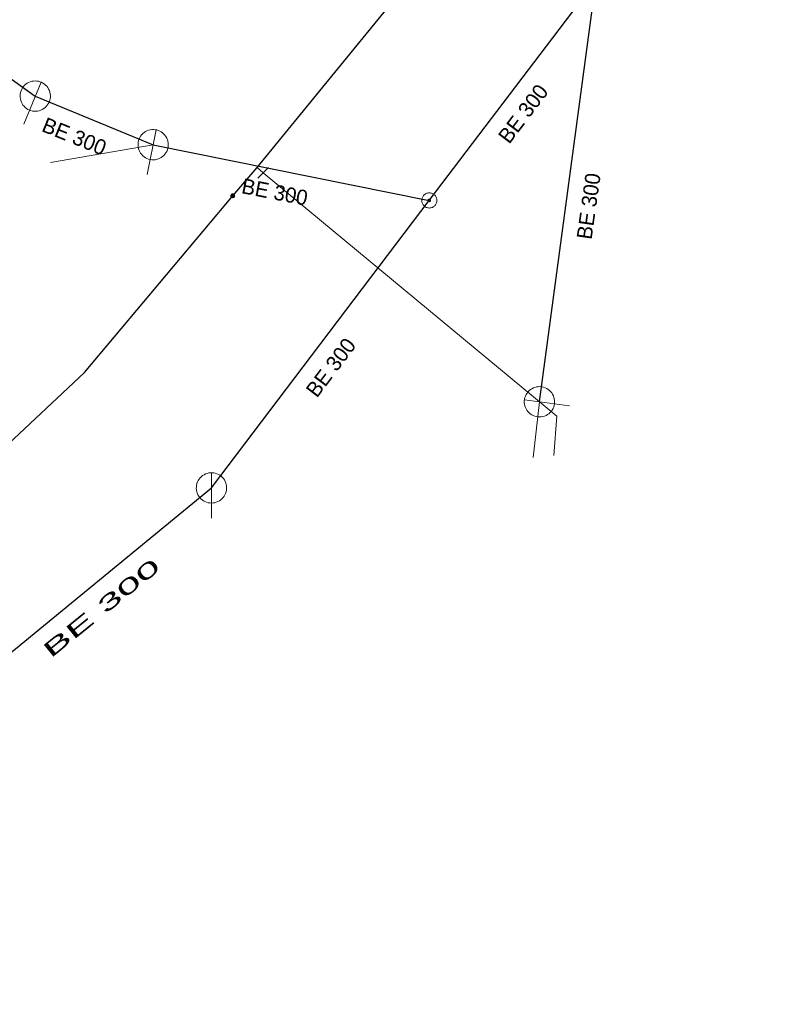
# Model space of a CAD drawing. Extents: x -791337 to -790755, y -988454 to -987923.
# Drawn here: x -791030.1 to -790980, y -988179.4 to -988115.1 of the extents above; entities that cross this region are included whole.
import ezdxf

# ---------------------------------------------------------------- set-up
doc = ezdxf.new("R2010")
doc.units = 0
doc.header["$LTSCALE"] = 0.4
for name, color, linetype, lineweight in [('1', 7, 'Continuous', 13), ('11', 7, 'Continuous', 13), ('13', 7, 'Continuous', 13), ('14', 7, 'Continuous', 25), ('17', 7, 'Continuous', 25), ('22', 7, 'Continuous', 13), ('31', 7, 'Continuous', 13), ('34', 7, 'Continuous', 13), ('9', 7, 'Continuous', 13)]:
    doc.layers.add(name, color=color, linetype=linetype, lineweight=lineweight)

msp = doc.modelspace()

# ---------------------------------------------------------------- linework, layer by layer
at = {"layer": '11'}
for p, q in [((-791028.011, -988124.594), (-791021.247, -988123.414)), ((-790996.191, -988144.061), (-790995.768, -988140.376))]:
    msp.add_line(p, q, dxfattribs=at)
at = {"layer": '13'}
msp.add_line((-791014.379, -988124.914), (-791013.989, -988125.269), dxfattribs=at)
msp.add_lwpolyline([(-791013.989, -988125.269), (-790994.62, -988141.329), (-790994.829, -988143.927)], dxfattribs=at)
at = {"layer": '14'}
for p, q in [((-790995.768, -988140.376), (-790992.035, -988112.568)), ((-791017.401, -988146.056), (-791003.034, -988127.09))]:
    msp.add_line(p, q, dxfattribs=at)
for points in [[(-791003.034, -988127.09), (-790992.035, -988112.568), (-790980, -988098.359)], [(-791052.439, -988139.196), (-791035.28, -988115.732), (-791029.024, -988120.205)], [(-791029.024, -988120.205), (-791021.247, -988123.414), (-791003.034, -988127.09)], [(-791038.46, -988179.417), (-791036.499, -988161.736), (-791017.401, -988146.056)]]:
    msp.add_lwpolyline(points, dxfattribs=at)
at = {"layer": '17'}
for points in [[(-791015.996, -988126.782), (-791014.379, -988124.914), (-791004.537, -988112.846), (-790993.489, -988096.87), (-790985.039, -988083.809)], [(-791058.988, -988167.736), (-791047.931, -988158.352), (-791041.594, -988153.292), (-791025.772, -988138.449), (-791015.996, -988126.782)]]:
    msp.add_lwpolyline(points, dxfattribs=at)
at = {"layer": '22'}
for p, q in [((-791029.786, -988122.054), (-791028.642, -988119.281)), ((-791021.642, -988125.374), (-791021.049, -988122.434)), ((-790993.785, -988140.642), (-790996.758, -988140.242)), ((-791017.401, -988148.056), (-791017.4, -988145.056))]:
    msp.add_line(p, q, dxfattribs=at)
for points in [[(-791028.099, -988120.586), (-791028.063, -988120.483), (-791028.039, -988120.377), (-791028.026, -988120.267), (-791028.024, -988120.158), (-791028.036, -988120.049), (-791028.059, -988119.942), (-791028.093, -988119.838), (-791028.139, -988119.739), (-791028.195, -988119.644), (-791028.261, -988119.558), (-791028.337, -988119.478), (-791028.421, -988119.408), (-791028.512, -988119.346), (-791028.609, -988119.296), (-791028.711, -988119.255), (-791028.816, -988119.227), (-791028.925, -988119.21), (-791029.034, -988119.204), (-791029.143, -988119.212), (-791029.25, -988119.231), (-791029.356, -988119.262), (-791029.457, -988119.304), (-791029.553, -988119.357), (-791029.643, -988119.419), (-791029.725, -988119.492), (-791029.798, -988119.573), (-791029.863, -988119.662), (-791029.917, -988119.756), (-791029.961, -988119.857), (-791029.993, -988119.962), (-791030.015, -988120.069), (-791030.023, -988120.178), (-791030.02, -988120.287), (-791030.006, -988120.396), (-791029.978, -988120.502), (-791029.94, -988120.605), (-791029.891, -988120.703), (-791029.832, -988120.794), (-791029.763, -988120.879), (-791029.684, -988120.956), (-791029.598, -988121.024), (-791029.505, -988121.082), (-791029.406, -988121.129), (-791029.303, -988121.165), (-791029.196, -988121.19), (-791029.088, -988121.203), (-791028.978, -988121.204), (-791028.869, -988121.193), (-791028.762, -988121.17), (-791028.658, -988121.136), (-791028.558, -988121.09), (-791028.465, -988121.034), (-791028.377, -988120.968), (-791028.298, -988120.893), (-791028.227, -988120.809), (-791028.165, -988120.718), (-791028.115, -988120.621)], [(-791020.266, -988123.612), (-791020.251, -988123.504), (-791020.247, -988123.394), (-791020.255, -988123.285), (-791020.275, -988123.178), (-791020.306, -988123.072), (-791020.349, -988122.972), (-791020.403, -988122.876), (-791020.467, -988122.788), (-791020.54, -988122.706), (-791020.622, -988122.633), (-791020.711, -988122.569), (-791020.807, -988122.516), (-791020.908, -988122.473), (-791021.013, -988122.442), (-791021.121, -988122.422), (-791021.229, -988122.415), (-791021.339, -988122.418), (-791021.448, -988122.434), (-791021.553, -988122.462), (-791021.655, -988122.501), (-791021.753, -988122.552), (-791021.844, -988122.612), (-791021.928, -988122.683), (-791022.004, -988122.761), (-791022.071, -988122.848), (-791022.127, -988122.941), (-791022.174, -988123.041), (-791022.209, -988123.144), (-791022.233, -988123.252), (-791022.245, -988123.36), (-791022.245, -988123.469), (-791022.233, -988123.578), (-791022.209, -988123.685), (-791022.174, -988123.789), (-791022.127, -988123.888), (-791022.07, -988123.981), (-791022.003, -988124.068), (-791021.927, -988124.147), (-791021.843, -988124.217), (-791021.751, -988124.277), (-791021.654, -988124.327), (-791021.552, -988124.366), (-791021.445, -988124.394), (-791021.337, -988124.41), (-791021.228, -988124.413), (-791021.119, -988124.406), (-791021.011, -988124.386), (-791020.906, -988124.354), (-791020.805, -988124.311), (-791020.71, -988124.258), (-791020.621, -988124.194), (-791020.54, -988124.121), (-791020.466, -988124.04), (-791020.403, -988123.951), (-791020.349, -988123.855), (-791020.306, -988123.754), (-791020.275, -988123.649)], [(-790995.634, -988139.384), (-790995.743, -988139.376), (-790995.852, -988139.379), (-790995.961, -988139.395), (-790996.067, -988139.421), (-790996.17, -988139.46), (-790996.267, -988139.509), (-790996.359, -988139.57), (-790996.443, -988139.639), (-790996.52, -988139.717), (-790996.587, -988139.803), (-790996.645, -988139.896), (-790996.692, -988139.996), (-790996.728, -988140.099), (-790996.752, -988140.206), (-790996.765, -988140.315), (-790996.765, -988140.424), (-790996.755, -988140.534), (-790996.732, -988140.641), (-790996.696, -988140.744), (-790996.651, -988140.843), (-790996.594, -988140.937), (-790996.528, -988141.024), (-790996.452, -988141.104), (-790996.369, -988141.175), (-790996.278, -988141.235), (-790996.181, -988141.286), (-790996.078, -988141.326), (-790995.973, -988141.354), (-790995.864, -988141.37), (-790995.755, -988141.375), (-790995.646, -988141.368), (-790995.538, -988141.349), (-790995.434, -988141.318), (-790995.332, -988141.276), (-790995.236, -988141.223), (-790995.147, -988141.16), (-790995.064, -988141.087), (-790994.991, -988141.006), (-790994.927, -988140.918), (-790994.873, -988140.823), (-790994.829, -988140.723), (-790994.797, -988140.618), (-790994.776, -988140.51), (-790994.767, -988140.401), (-790994.771, -988140.291), (-790994.786, -988140.183), (-790994.813, -988140.077), (-790994.851, -988139.974), (-790994.901, -988139.876), (-790994.96, -988139.785), (-790995.029, -988139.7), (-790995.108, -988139.624), (-790995.194, -988139.556), (-790995.287, -988139.499), (-790995.386, -988139.451), (-790995.49, -988139.415), (-790995.596, -988139.391)], [(-791016.401, -988146.056), (-791016.406, -988145.947), (-791016.424, -988145.839), (-791016.454, -988145.733), (-791016.494, -988145.632), (-791016.546, -988145.535), (-791016.608, -988145.445), (-791016.68, -988145.362), (-791016.76, -988145.288), (-791016.848, -988145.222), (-791016.942, -988145.167), (-791017.042, -988145.122), (-791017.147, -988145.089), (-791017.254, -988145.067), (-791017.363, -988145.057), (-791017.473, -988145.059), (-791017.581, -988145.073), (-791017.688, -988145.098), (-791017.791, -988145.135), (-791017.889, -988145.184), (-791017.981, -988145.242), (-791018.067, -988145.311), (-791018.144, -988145.388), (-791018.213, -988145.474), (-791018.272, -988145.566), (-791018.32, -988145.664), (-791018.357, -988145.767), (-791018.383, -988145.874), (-791018.397, -988145.982), (-791018.4, -988146.092), (-791018.39, -988146.201), (-791018.369, -988146.308), (-791018.335, -988146.412), (-791018.291, -988146.512), (-791018.236, -988146.607), (-791018.17, -988146.695), (-791018.096, -988146.775), (-791018.013, -988146.847), (-791017.923, -988146.909), (-791017.827, -988146.961), (-791017.725, -988147.002), (-791017.62, -988147.032), (-791017.512, -988147.05), (-791017.402, -988147.056), (-791017.293, -988147.05), (-791017.185, -988147.032), (-791017.08, -988147.003), (-791016.978, -988146.962), (-791016.881, -988146.91), (-791016.791, -988146.848), (-791016.708, -988146.777), (-791016.633, -988146.697), (-791016.568, -988146.609), (-791016.512, -988146.515), (-791016.468, -988146.415), (-791016.434, -988146.311), (-791016.412, -988146.203), (-791016.402, -988146.094)]]:
    msp.add_lwpolyline(points, close=True, dxfattribs=at)
at = {"layer": '31'}
for points in [[(-791002.543, -988127.188), (-791002.536, -988127.137), (-791002.534, -988127.084), (-791002.537, -988127.033), (-791002.545, -988126.981), (-791002.56, -988126.93), (-791002.579, -988126.881), (-791002.604, -988126.836), (-791002.633, -988126.792), (-791002.665, -988126.752), (-791002.703, -988126.715), (-791002.744, -988126.682), (-791002.789, -988126.654), (-791002.835, -988126.631), (-791002.884, -988126.613), (-791002.935, -988126.599), (-791002.986, -988126.592), (-791003.039, -988126.59), (-791003.091, -988126.593), (-791003.142, -988126.601), (-791003.193, -988126.616), (-791003.242, -988126.635), (-791003.288, -988126.66), (-791003.332, -988126.688), (-791003.372, -988126.721), (-791003.408, -988126.759), (-791003.441, -988126.8), (-791003.47, -988126.844), (-791003.492, -988126.891), (-791003.51, -988126.94), (-791003.524, -988126.991), (-791003.531, -988127.042), (-791003.533, -988127.095), (-791003.531, -988127.147), (-791003.522, -988127.198), (-791003.507, -988127.249), (-791003.489, -988127.298), (-791003.464, -988127.344), (-791003.435, -988127.388), (-791003.402, -988127.428), (-791003.364, -988127.464), (-791003.323, -988127.497), (-791003.28, -988127.525), (-791003.232, -988127.548), (-791003.183, -988127.566), (-791003.132, -988127.58), (-791003.081, -988127.587), (-791003.028, -988127.589), (-791002.977, -988127.587), (-791002.925, -988127.578), (-791002.874, -988127.563), (-791002.825, -988127.545), (-791002.78, -988127.52), (-791002.736, -988127.491), (-791002.696, -988127.458), (-791002.659, -988127.42), (-791002.626, -988127.379), (-791002.599, -988127.335), (-791002.575, -988127.288), (-791002.557, -988127.239)], [(-791002.953, -988127.106), (-791002.951, -988127.097), (-791002.952, -988127.089), (-791002.952, -988127.08), (-791002.953, -988127.072), (-791002.956, -988127.063), (-791002.959, -988127.056), (-791002.963, -988127.048), (-791002.968, -988127.041), (-791002.973, -988127.034), (-791002.979, -988127.028), (-791002.986, -988127.023), (-791002.994, -988127.018), (-791003.001, -988127.014), (-791003.008, -988127.011), (-791003.017, -988127.009), (-791003.026, -988127.007), (-791003.034, -988127.008), (-791003.043, -988127.008), (-791003.051, -988127.009), (-791003.06, -988127.012), (-791003.067, -988127.015), (-791003.075, -988127.019), (-791003.082, -988127.024), (-791003.09, -988127.029), (-791003.095, -988127.035), (-791003.1, -988127.042), (-791003.105, -988127.05), (-791003.109, -988127.057), (-791003.112, -988127.064), (-791003.114, -988127.073), (-791003.116, -988127.082), (-791003.115, -988127.09), (-791003.115, -988127.099), (-791003.114, -988127.107), (-791003.111, -988127.116), (-791003.109, -988127.123), (-791003.104, -988127.131), (-791003.099, -988127.138), (-791003.094, -988127.146), (-791003.088, -988127.151), (-791003.081, -988127.156), (-791003.073, -988127.161), (-791003.066, -988127.165), (-791003.059, -988127.168), (-791003.05, -988127.17), (-791003.041, -988127.172), (-791003.033, -988127.171), (-791003.024, -988127.171), (-791003.016, -988127.17), (-791003.007, -988127.167), (-791003, -988127.165), (-791002.992, -988127.16), (-791002.985, -988127.155), (-791002.978, -988127.15), (-791002.972, -988127.144), (-791002.967, -988127.137), (-791002.962, -988127.129), (-791002.958, -988127.122), (-791002.955, -988127.115)]]:
    msp.add_lwpolyline(points, close=True, dxfattribs=at)
at = {"layer": '34'}
msp.add_line((-791013.635, -988124.915), (-791014.343, -988125.621), dxfattribs=at)
at = {"layer": '9'}
for points in [[(-791016.122, -988126.782), (-791016.122, -988126.795), (-791016.12, -988126.808), (-791016.117, -988126.821), (-791016.112, -988126.833), (-791016.106, -988126.845), (-791016.099, -988126.856), (-791016.091, -988126.866), (-791016.081, -988126.876), (-791016.071, -988126.884), (-791016.06, -988126.891), (-791016.048, -988126.897), (-791016.036, -988126.902), (-791016.023, -988126.905), (-791016.01, -988126.907), (-791015.997, -988126.909), (-791015.984, -988126.908), (-791015.971, -988126.906), (-791015.958, -988126.903), (-791015.946, -988126.898), (-791015.934, -988126.892), (-791015.923, -988126.885), (-791015.913, -988126.877), (-791015.903, -988126.867), (-791015.895, -988126.857), (-791015.888, -988126.846), (-791015.882, -988126.834), (-791015.877, -988126.822), (-791015.874, -988126.809), (-791015.872, -988126.796), (-791015.87, -988126.783), (-791015.871, -988126.77), (-791015.873, -988126.757), (-791015.876, -988126.744), (-791015.881, -988126.732), (-791015.887, -988126.72), (-791015.894, -988126.709), (-791015.902, -988126.699), (-791015.912, -988126.689), (-791015.922, -988126.681), (-791015.933, -988126.674), (-791015.945, -988126.668), (-791015.957, -988126.663), (-791015.97, -988126.66), (-791015.983, -988126.658), (-791015.996, -988126.657), (-791016.009, -988126.657), (-791016.022, -988126.659), (-791016.035, -988126.662), (-791016.047, -988126.667), (-791016.059, -988126.673), (-791016.07, -988126.68), (-791016.08, -988126.688), (-791016.09, -988126.698), (-791016.098, -988126.708), (-791016.105, -988126.719), (-791016.111, -988126.731), (-791016.116, -988126.743), (-791016.119, -988126.756), (-791016.121, -988126.769)], [(-791016.102, -988126.782), (-791016.103, -988126.793), (-791016.101, -988126.804), (-791016.098, -988126.815), (-791016.094, -988126.825), (-791016.089, -988126.835), (-791016.083, -988126.844), (-791016.076, -988126.853), (-791016.068, -988126.861), (-791016.059, -988126.868), (-791016.05, -988126.874), (-791016.04, -988126.879), (-791016.03, -988126.883), (-791016.019, -988126.886), (-791016.008, -988126.889), (-791015.997, -988126.889), (-791015.986, -988126.889), (-791015.975, -988126.887), (-791015.964, -988126.884), (-791015.954, -988126.88), (-791015.944, -988126.875), (-791015.935, -988126.869), (-791015.926, -988126.862), (-791015.918, -988126.854), (-791015.911, -988126.845), (-791015.905, -988126.836), (-791015.9, -988126.826), (-791015.896, -988126.816), (-791015.893, -988126.805), (-791015.891, -988126.794), (-791015.89, -988126.783), (-791015.89, -988126.772), (-791015.892, -988126.761), (-791015.895, -988126.75), (-791015.899, -988126.74), (-791015.904, -988126.73), (-791015.91, -988126.721), (-791015.917, -988126.712), (-791015.925, -988126.704), (-791015.934, -988126.697), (-791015.943, -988126.691), (-791015.953, -988126.686), (-791015.963, -988126.682), (-791015.974, -988126.679), (-791015.985, -988126.677), (-791015.996, -988126.677), (-791016.007, -988126.676), (-791016.018, -988126.678), (-791016.029, -988126.681), (-791016.039, -988126.685), (-791016.049, -988126.69), (-791016.058, -988126.696), (-791016.067, -988126.703), (-791016.075, -988126.711), (-791016.082, -988126.72), (-791016.088, -988126.729), (-791016.093, -988126.739), (-791016.097, -988126.749), (-791016.1, -988126.76), (-791016.102, -988126.771)], [(-791016.083, -988126.782), (-791016.083, -988126.791), (-791016.082, -988126.8), (-791016.079, -988126.809), (-791016.076, -988126.817), (-791016.072, -988126.825), (-791016.067, -988126.833), (-791016.061, -988126.84), (-791016.055, -988126.846), (-791016.048, -988126.852), (-791016.04, -988126.857), (-791016.032, -988126.861), (-791016.024, -988126.864), (-791016.015, -988126.867), (-791016.006, -988126.868), (-791015.997, -988126.87), (-791015.988, -988126.869), (-791015.979, -988126.868), (-791015.97, -988126.865), (-791015.962, -988126.862), (-791015.954, -988126.858), (-791015.946, -988126.853), (-791015.939, -988126.847), (-791015.933, -988126.841), (-791015.927, -988126.834), (-791015.922, -988126.826), (-791015.918, -988126.818), (-791015.915, -988126.81), (-791015.912, -988126.801), (-791015.911, -988126.792), (-791015.909, -988126.783), (-791015.91, -988126.774), (-791015.911, -988126.765), (-791015.914, -988126.756), (-791015.917, -988126.748), (-791015.921, -988126.74), (-791015.926, -988126.732), (-791015.932, -988126.725), (-791015.938, -988126.719), (-791015.945, -988126.713), (-791015.953, -988126.708), (-791015.961, -988126.704), (-791015.969, -988126.701), (-791015.978, -988126.698), (-791015.987, -988126.697), (-791015.996, -988126.696), (-791016.005, -988126.696), (-791016.014, -988126.697), (-791016.023, -988126.7), (-791016.031, -988126.703), (-791016.039, -988126.707), (-791016.047, -988126.712), (-791016.054, -988126.718), (-791016.06, -988126.724), (-791016.066, -988126.731), (-791016.071, -988126.739), (-791016.075, -988126.747), (-791016.078, -988126.755), (-791016.081, -988126.764), (-791016.082, -988126.773)], [(-791016.063, -988126.782), (-791016.063, -988126.789), (-791016.062, -988126.796), (-791016.061, -988126.803), (-791016.058, -988126.809), (-791016.055, -988126.815), (-791016.051, -988126.821), (-791016.047, -988126.827), (-791016.042, -988126.832), (-791016.036, -988126.836), (-791016.03, -988126.84), (-791016.024, -988126.843), (-791016.018, -988126.846), (-791016.011, -988126.847), (-791016.004, -988126.85), (-791015.997, -988126.85), (-791015.99, -988126.85), (-791015.983, -988126.848), (-791015.976, -988126.847), (-791015.97, -988126.844), (-791015.963, -988126.841), (-791015.958, -988126.837), (-791015.952, -988126.833), (-791015.947, -988126.828), (-791015.943, -988126.822), (-791015.939, -988126.816), (-791015.936, -988126.81), (-791015.933, -988126.804), (-791015.931, -988126.797), (-791015.93, -988126.79), (-791015.929, -988126.783), (-791015.929, -988126.776), (-791015.93, -988126.769), (-791015.932, -988126.762), (-791015.935, -988126.756), (-791015.938, -988126.749), (-791015.942, -988126.744), (-791015.946, -988126.738), (-791015.951, -988126.733), (-791015.957, -988126.729), (-791015.962, -988126.725), (-791015.969, -988126.722), (-791015.975, -988126.719), (-791015.982, -988126.717), (-791015.989, -988126.716), (-791015.996, -988126.716), (-791016.003, -988126.716), (-791016.01, -988126.716), (-791016.017, -988126.718), (-791016.023, -988126.721), (-791016.029, -988126.724), (-791016.035, -988126.728), (-791016.041, -988126.732), (-791016.046, -988126.737), (-791016.05, -988126.743), (-791016.054, -988126.748), (-791016.057, -988126.755), (-791016.06, -988126.761), (-791016.061, -988126.768), (-791016.063, -988126.775)], [(-791016.043, -988126.782), (-791016.043, -988126.787), (-791016.043, -988126.792), (-791016.042, -988126.797), (-791016.04, -988126.801), (-791016.038, -988126.806), (-791016.035, -988126.81), (-791016.032, -988126.813), (-791016.028, -988126.817), (-791016.025, -988126.82), (-791016.021, -988126.823), (-791016.016, -988126.825), (-791016.012, -988126.827), (-791016.007, -988126.828), (-791016.002, -988126.83), (-791015.997, -988126.83), (-791015.992, -988126.83), (-791015.987, -988126.829), (-791015.982, -988126.828), (-791015.978, -988126.826), (-791015.973, -988126.824), (-791015.969, -988126.821), (-791015.965, -988126.818), (-791015.962, -988126.814), (-791015.959, -988126.811), (-791015.956, -988126.807), (-791015.954, -988126.802), (-791015.952, -988126.798), (-791015.951, -988126.793), (-791015.95, -988126.788), (-791015.949, -988126.783), (-791015.949, -988126.778), (-791015.95, -988126.773), (-791015.951, -988126.768), (-791015.953, -988126.764), (-791015.955, -988126.759), (-791015.958, -988126.755), (-791015.961, -988126.751), (-791015.964, -988126.748), (-791015.968, -988126.745), (-791015.972, -988126.742), (-791015.977, -988126.74), (-791015.981, -988126.738), (-791015.986, -988126.737), (-791015.991, -988126.736), (-791015.996, -988126.736), (-791016.001, -988126.736), (-791016.006, -988126.737), (-791016.011, -988126.737), (-791016.015, -988126.739), (-791016.02, -988126.741), (-791016.024, -988126.744), (-791016.027, -988126.747), (-791016.031, -988126.75), (-791016.034, -988126.754), (-791016.037, -988126.758), (-791016.039, -988126.763), (-791016.041, -988126.767), (-791016.042, -988126.772), (-791016.043, -988126.777)], [(-791016.023, -988126.782), (-791016.023, -988126.785), (-791016.024, -988126.788), (-791016.023, -988126.79), (-791016.022, -988126.793), (-791016.021, -988126.796), (-791016.019, -988126.798), (-791016.017, -988126.8), (-791016.015, -988126.802), (-791016.013, -988126.804), (-791016.011, -988126.806), (-791016.008, -988126.808), (-791016.005, -988126.809), (-791016.003, -988126.809), (-791016, -988126.81), (-791015.997, -988126.81), (-791015.994, -988126.81), (-791015.991, -988126.81), (-791015.988, -988126.809), (-791015.986, -988126.808), (-791015.983, -988126.807), (-791015.981, -988126.805), (-791015.978, -988126.803), (-791015.976, -988126.801), (-791015.975, -988126.799), (-791015.973, -988126.797), (-791015.972, -988126.794), (-791015.97, -988126.791), (-791015.97, -988126.789), (-791015.969, -988126.786), (-791015.968, -988126.783), (-791015.969, -988126.78), (-791015.969, -988126.777), (-791015.97, -988126.774), (-791015.971, -988126.772), (-791015.972, -988126.769), (-791015.974, -988126.767), (-791015.975, -988126.764), (-791015.977, -988126.762), (-791015.98, -988126.761), (-791015.982, -988126.759), (-791015.985, -988126.758), (-791015.987, -988126.757), (-791015.99, -988126.756), (-791015.993, -988126.756), (-791015.996, -988126.755), (-791015.999, -988126.756), (-791016.002, -988126.755), (-791016.004, -988126.757), (-791016.007, -988126.757), (-791016.01, -988126.758), (-791016.012, -988126.76), (-791016.014, -988126.761), (-791016.016, -988126.763), (-791016.018, -988126.766), (-791016.02, -988126.768), (-791016.021, -988126.771), (-791016.022, -988126.773), (-791016.023, -988126.776), (-791016.023, -988126.779)], [(-791016.004, -988126.782), (-791016.004, -988126.784), (-791016.004, -988126.784), (-791016.003, -988126.784), (-791016.003, -988126.786), (-791016.004, -988126.787), (-791016.002, -988126.787), (-791016.002, -988126.787), (-791016.002, -988126.789), (-791016.002, -988126.789), (-791016.001, -988126.79), (-791015.999, -988126.79), (-791015.999, -988126.79), (-791015.999, -988126.791), (-791015.997, -988126.791), (-791015.997, -988126.791), (-791015.996, -988126.791), (-791015.995, -988126.791), (-791015.995, -988126.79), (-791015.994, -988126.79), (-791015.992, -988126.79), (-791015.992, -988126.789), (-791015.992, -988126.789), (-791015.991, -988126.788), (-791015.991, -988126.788), (-791015.989, -988126.787), (-791015.989, -988126.786), (-791015.988, -988126.785), (-791015.988, -988126.785), (-791015.988, -988126.784), (-791015.988, -988126.783), (-791015.988, -988126.782), (-791015.988, -988126.781), (-791015.988, -988126.781), (-791015.989, -988126.78), (-791015.989, -988126.779), (-791015.99, -988126.778), (-791015.99, -988126.778), (-791015.991, -988126.777), (-791015.991, -988126.777), (-791015.992, -988126.776), (-791015.993, -988126.776), (-791015.994, -988126.775), (-791015.994, -988126.775), (-791015.995, -988126.775), (-791015.996, -988126.775), (-791015.997, -988126.775), (-791015.998, -988126.775), (-791015.998, -988126.775), (-791015.999, -988126.776), (-791016, -988126.775), (-791016.001, -988126.777), (-791016.001, -988126.777), (-791016.002, -988126.777), (-791016.002, -988126.777), (-791016.003, -988126.779), (-791016.003, -988126.78), (-791016.003, -988126.781), (-791016.004, -988126.781), (-791016.004, -988126.782)]]:
    msp.add_lwpolyline(points, close=True, dxfattribs=at)

# ---------------------------------------------------------------- texts
at = {"layer": '1'}
for rotation, p in [(53, (-790997.762, -988123.419)), (338, (-791028.665, -988122.5)), (349, (-791015.474, -988126.604)), (82, (-790992.332, -988129.709)), (53, (-791010.445, -988140.163))]:
    msp.add_text('BE 300', height=1, rotation=rotation, dxfattribs=at).set_placement(p)
at = {"layer": '1', "width": 2.15}
msp.add_text('BE 300', height=1, rotation=39, dxfattribs=at).set_placement((-791028.008, -988157.334))

doc.saveas('drawing.dxf')
